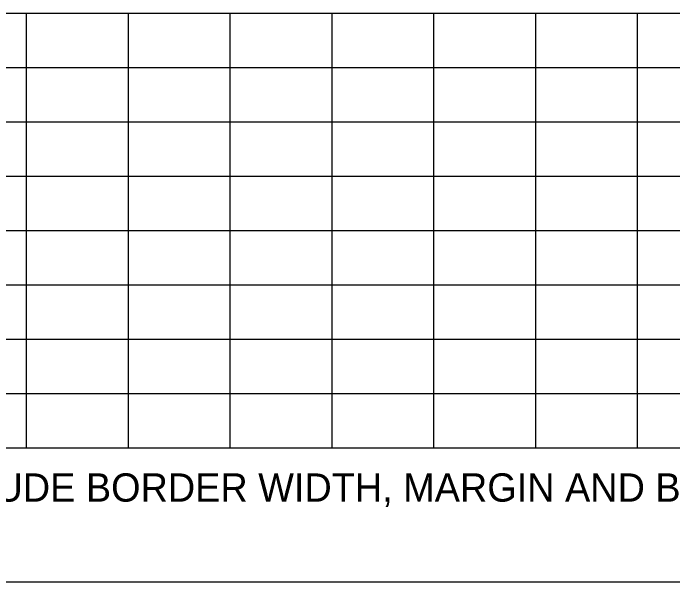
# Model space of a CAD drawing. Extents: x 10268312 to 10268472, y 2142583 to 2142688.
# Drawn here: x 10268413.59 to 10268433.03, y 2142640.28 to 2142657.03 of the extents above; entities that cross this region are included whole.
import ezdxf

# ---------------------------------------------------------------- set-up
doc = ezdxf.new("R2010")
doc.units = 0
for name, color, linetype in [('SheetBorder_dp', 7, 'Continuous'), ('SumBoxLines_dp', 7, 'Continuous'), ('SumBoxLinesMin_dp', 7, 'Continuous'), ('TextNotes', 7, 'Continuous')]:
    doc.layers.add(name, color=color, linetype=linetype)

msp = doc.modelspace()

# ---------------------------------------------------------------- linework, layer by layer
at = {"layer": 'SheetBorder_dp'}
msp.add_line((10268317.73, 2142640.282), (10268471.73, 2142640.282), dxfattribs=at)
at = {"layer": 'SumBoxLines_dp'}
for p, q in [((10268395.48, 2142657.032), (10268470.98, 2142657.032)), ((10268413.98, 2142657.032), (10268413.98, 2142653.832)), ((10268416.98, 2142657.032), (10268416.98, 2142653.832)), ((10268419.98, 2142657.032), (10268419.98, 2142655.432)), ((10268422.98, 2142657.032), (10268422.98, 2142653.832)), ((10268425.98, 2142657.032), (10268425.98, 2142653.832)), ((10268428.98, 2142657.032), (10268428.98, 2142653.832)), ((10268431.98, 2142657.032), (10268431.98, 2142653.832)), ((10268419.98, 2142655.432), (10268419.98, 2142650.632)), ((10268395.48, 2142653.832), (10268470.98, 2142653.832)), ((10268413.98, 2142653.832), (10268413.98, 2142647.432)), ((10268416.98, 2142653.832), (10268416.98, 2142650.632)), ((10268422.98, 2142653.832), (10268422.98, 2142650.632)), ((10268425.98, 2142653.832), (10268425.98, 2142650.632)), ((10268428.98, 2142653.832), (10268428.98, 2142650.632)), ((10268431.98, 2142653.832), (10268431.98, 2142649.032)), ((10268395.48, 2142650.632), (10268470.98, 2142650.632)), ((10268416.98, 2142650.632), (10268416.98, 2142647.432)), ((10268419.98, 2142650.632), (10268419.98, 2142647.432)), ((10268422.98, 2142650.632), (10268422.98, 2142647.432)), ((10268425.98, 2142650.632), (10268425.98, 2142647.432)), ((10268428.98, 2142650.632), (10268428.98, 2142647.432)), ((10268431.98, 2142649.032), (10268431.98, 2142644.232)), ((10268395.48, 2142647.432), (10268470.98, 2142647.432)), ((10268413.98, 2142647.432), (10268413.98, 2142644.232)), ((10268416.98, 2142647.432), (10268416.98, 2142644.232)), ((10268419.98, 2142647.432), (10268419.98, 2142644.232)), ((10268422.98, 2142647.432), (10268422.98, 2142644.232)), ((10268425.98, 2142647.432), (10268425.98, 2142644.232)), ((10268428.98, 2142647.432), (10268428.98, 2142644.232)), ((10268395.48, 2142644.232), (10268470.98, 2142644.232))]:
    msp.add_line(p, q, dxfattribs=at)
at = {"layer": 'SumBoxLinesMin_dp'}
for p, q in [((10268395.48, 2142655.432), (10268470.98, 2142655.432)), ((10268395.48, 2142652.232), (10268470.98, 2142652.232)), ((10268395.48, 2142649.032), (10268470.98, 2142649.032)), ((10268395.48, 2142645.832), (10268470.98, 2142645.832))]:
    msp.add_line(p, q, dxfattribs=at)

# ---------------------------------------------------------------- texts
at = {"layer": 'TextNotes'}
msp.add_text('NOTE:  END DIMENSIONS INCLUDE BORDER WIDTH, MARGIN AND BORDER RECESS.  ', height=0.83333, dxfattribs=at).set_placement((10268396.479, 2142642.643))

doc.saveas('drawing.dxf')
